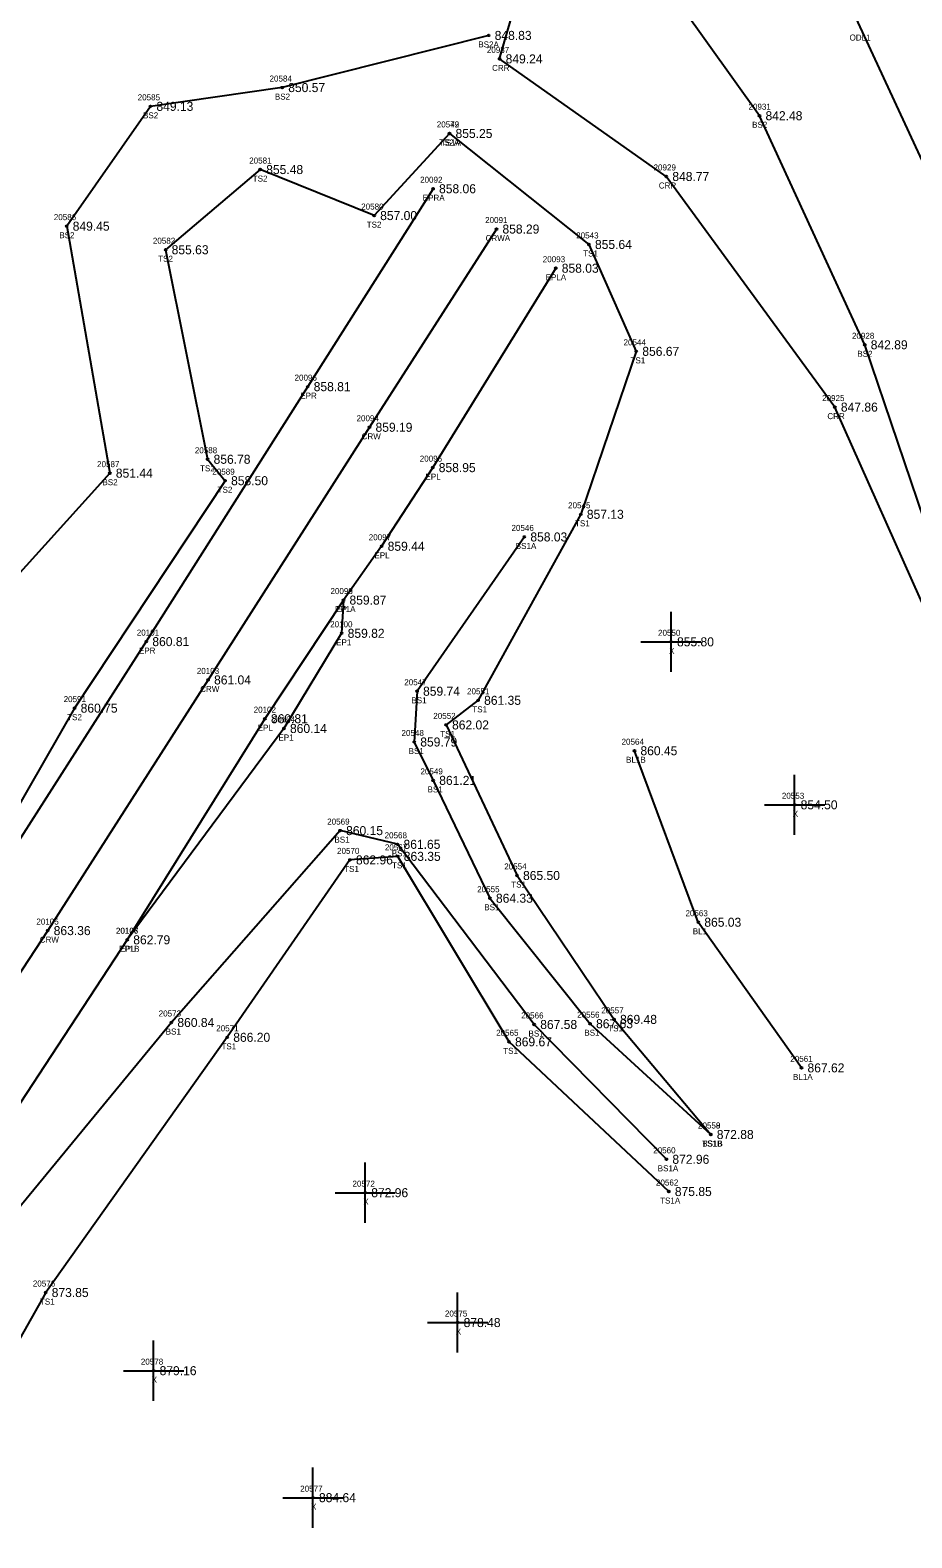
# Model space of a CAD drawing. Extents: x 1394668 to 1397182, y 1073212 to 1074501.
# Drawn here: x 1395802.6 to 1395949.1, y 1073687.4 to 1073938.1 of the extents above; entities that cross this region are included whole.
import ezdxf

# ---------------------------------------------------------------- set-up
doc = ezdxf.new("R2010")
doc.units = 0
for name, color, linetype in [('RD_DTM_BkLn1', 7, 'Continuous'), ('RD_DTM_BkLn2', 7, 'Continuous'), ('RD_DTM_BkLn_txCode', 7, 'Continuous'), ('RD_EX_H2O', 7, 'Continuous'), ('RD_EX_H2O_txCode', 7, 'Continuous'), ('RD_EX_Misc', 7, 'Continuous'), ('RD_EX_Misc_txCode', 7, 'Continuous'), ('RD_EX_Road', 7, 'Continuous'), ('RD_EX_Road_txCode', 7, 'Continuous'), ('RD_EX_TX_H2O_ELEV', 7, 'Continuous'), ('RD_EX_TX_Misc_ELEV', 7, 'Continuous'), ('RD_EX_TX_Road_ELEV', 7, 'Continuous'), ('RD_HC_Survey_ELEV', 7, 'Continuous'), ('RD_HC_Survey_txCode', 7, 'Continuous'), ('RD_SMD_Locator', 7, 'Continuous')]:
    doc.layers.add(name, color=color, linetype=linetype)

msp = doc.modelspace()

# ---------------------------------------------------------------- linework, layer by layer
at = {"layer": 'RD_DTM_BkLn1'}
for points in [[(1395880.09, 1073905.01), (1395858.99, 1073872.06), (1395832.15, 1073830.06), (1395805.49, 1073788.39), (1395778.2, 1073746.79), (1395749.91, 1073705.5), (1395721.01, 1073665.07), (1395690.33, 1073625.47), (1395658.02, 1073587.64), (1395622.95, 1073551.76), (1395585.52, 1073519.1), (1395545.34, 1073489.25), (1395503.34, 1073462.75), (1395459.17, 1073438.88), (1395413.72, 1073418.7), (1395366.56, 1073401.38), (1395319.05, 1073387), (1395269.86, 1073375.63), (1395220.56, 1073368.3)], [(1395930.8, 1073765.57), (1395913.65, 1073789.78), (1395903.03, 1073818.29)]]:
    msp.add_lwpolyline(points, dxfattribs=at)
at = {"layer": 'RD_DTM_BkLn2'}
for points in [[(1395957.8, 1073837.25), (1395941.31, 1073885.77), (1395923.82, 1073923.85), (1395893.58, 1073966.14), (1395870.08, 1073993.52)], [(1395878.8, 1073937.2), (1395844.48, 1073928.53), (1395822.57, 1073925.41), (1395808.65, 1073905.49), (1395815.82, 1073864.43), (1395791.04, 1073837.08), (1395769.09, 1073795.23), (1395741.94, 1073761.37), (1395712.42, 1073733.44), (1395686.92, 1073719.11), (1395655.83, 1073688.97), (1395630.94, 1073651.62), (1395607.03, 1073620.68), (1395575.39, 1073568.35), (1395560.35, 1073553.89), (1395550.78, 1073525.35), (1395509.42, 1073493.18)], [(1395872.29, 1073920.9), (1395859.76, 1073907.25), (1395840.82, 1073914.9), (1395825.1, 1073901.57), (1395832.07, 1073866.74), (1395834.98, 1073863.18), (1395809.97, 1073825.37), (1395786.91, 1073785.27), (1395760.58, 1073746.02), (1395733.77, 1073707.72), (1395713.02, 1073697.84), (1395686.96, 1073656.85), (1395662.51, 1073616.18), (1395631.74, 1073579.72), (1395598.58, 1073547.6), (1395556.36, 1073515.78), (1395517.25, 1073487.44)], [(1395872.29, 1073920.9), (1395895.47, 1073902.45), (1395903.34, 1073884.68), (1395894.12, 1073857.59), (1395877.04, 1073826.67), (1395871.71, 1073822.58), (1395883.51, 1073797.55), (1395899.64, 1073773.63), (1395915.72, 1073754.49)], [(1395884.73, 1073853.83), (1395866.89, 1073828.18), (1395866.43, 1073819.74), (1395869.58, 1073813.36), (1395879.01, 1073793.77), (1395895.65, 1073772.91), (1395915.72, 1073754.49)], [(1395908.34, 1073750.37), (1395886.37, 1073772.78), (1395863.64, 1073802.73), (1395854.1, 1073805.01), (1395826.05, 1073773.11), (1395793.87, 1073734.05), (1395764.78, 1073693.78), (1395736.01, 1073653.66), (1395704.56, 1073612.75), (1395670.33, 1073572.71), (1395637.43, 1073538.26), (1395595.47, 1073500.49), (1395545.21, 1073467.28)], [(1395908.75, 1073745.01), (1395882.18, 1073769.9), (1395863.69, 1073800.73), (1395855.74, 1073800.14), (1395835.34, 1073770.65), (1395805.16, 1073728.22), (1395777.09, 1073678.51), (1395754.62, 1073640.84), (1395721.66, 1073598.5), (1395682.88, 1073559.13), (1395644.57, 1073530.52), (1395608.93, 1073486.25), (1395561.12, 1073435.87)]]:
    msp.add_lwpolyline(points, dxfattribs=at)
at = {"layer": 'RD_EX_H2O'}
for points in [[(1395974.71, 1073847.23), (1395960.86, 1073894.92), (1395940.2, 1073939.35), (1395933.1, 1073958.35), (1395906.99, 1073983.95), (1395882.29, 1074009.48), (1395872.4, 1074025.84), (1395839.4, 1074068.55), (1395789.78, 1074092.35), (1395765.41, 1074131.47), (1395761.6, 1074177.86), (1395765.67, 1074225.67), (1395772.88, 1074279.07), (1395812.72, 1074333.02), (1395830.71, 1074357.92)], [(1395952, 1073840.27), (1395936.35, 1073875.41), (1395908.33, 1073913.75), (1395880.62, 1073933.3), (1395888.13, 1073959.38), (1395867.11, 1073990.5)]]:
    msp.add_lwpolyline(points, dxfattribs=at)
at = {"layer": 'RD_EX_Misc'}
for p, q in [((1395909.11, 1073831.39), (1395909.11, 1073841.39)), ((1395904.11, 1073836.39), (1395914.11, 1073836.39)), ((1395929.66, 1073804.3), (1395929.66, 1073814.3)), ((1395924.66, 1073809.3), (1395934.66, 1073809.3)), ((1395858.28, 1073739.82), (1395858.28, 1073749.82)), ((1395853.28, 1073744.82), (1395863.28, 1073744.82)), ((1395873.64, 1073718.23), (1395873.64, 1073728.23)), ((1395868.64, 1073723.23), (1395878.64, 1073723.23)), ((1395823.1, 1073710.23), (1395823.1, 1073720.23)), ((1395818.1, 1073715.23), (1395828.1, 1073715.23)), ((1395849.59, 1073689.12), (1395849.59, 1073699.12)), ((1395844.59, 1073694.12), (1395854.59, 1073694.12))]:
    msp.add_line(p, q, dxfattribs=at)
at = {"layer": 'RD_EX_Road'}
for points in [[(1395869.55, 1073911.71), (1395848.71, 1073878.81), (1395821.89, 1073836.43), (1395795.02, 1073794.57), (1395768.15, 1073753.29), (1395739.4, 1073711.73), (1395711.25, 1073671.91), (1395680.67, 1073632.3), (1395648.91, 1073595.47), (1395613.89, 1073559.5), (1395578.15, 1073528.43), (1395538.64, 1073499.26), (1395497.33, 1073473.22), (1395453.33, 1073449.12), (1395408.97, 1073429.57), (1395362.04, 1073412.34), (1395315.46, 1073398.44), (1395267.16, 1073387.31), (1395218.96, 1073380.11)], [(1395889.95, 1073898.5), (1395869.5, 1073865.35), (1395861.01, 1073852.28), (1395854.66, 1073843.33), (1395841.6, 1073823.61), (1395818.72, 1073786.86), (1395788.22, 1073740.4), (1395759.3, 1073697.79), (1395730.49, 1073656.98), (1395699.68, 1073617), (1395667.2, 1073579.48), (1395631.87, 1073543.45), (1395592.83, 1073509.92), (1395550.91, 1073478.97), (1395509.01, 1073452.5), (1395464.5, 1073428.26), (1395417.91, 1073407.56), (1395369.36, 1073389.54), (1395322.83, 1073375.66), (1395271.04, 1073363.5), (1395222.14, 1073356.32)], [(1395854.66, 1073843.33), (1395854.36, 1073837.81), (1395844.77, 1073821.99), (1395818.72, 1073786.86)]]:
    msp.add_lwpolyline(points, dxfattribs=at)
at = {"layer": 'RD_SMD_Locator'}
for centre in [(1395878.8, 1073937.2), (1395880.62, 1073933.3), (1395844.48, 1073928.53), (1395822.57, 1073925.41), (1395923.82, 1073923.85), (1395872.29, 1073920.9), (1395872.29, 1073920.9), (1395840.82, 1073914.9), (1395869.55, 1073911.71), (1395908.33, 1073913.75), (1395859.76, 1073907.25), (1395808.65, 1073905.49), (1395880.09, 1073905.01), (1395825.1, 1073901.57), (1395895.47, 1073902.45), (1395889.95, 1073898.5), (1395903.34, 1073884.68), (1395941.31, 1073885.77), (1395848.71, 1073878.81), (1395936.35, 1073875.41), (1395858.99, 1073872.06), (1395832.07, 1073866.74), (1395815.82, 1073864.43), (1395869.5, 1073865.35), (1395834.98, 1073863.18), (1395894.12, 1073857.59), (1395884.73, 1073853.83), (1395861.01, 1073852.28), (1395854.66, 1073843.33), (1395854.66, 1073843.33), (1395821.89, 1073836.43), (1395854.36, 1073837.81), (1395909.11, 1073836.39), (1395832.15, 1073830.06), (1395866.89, 1073828.18), (1395877.04, 1073826.67), (1395809.97, 1073825.37), (1395841.6, 1073823.61), (1395844.77, 1073821.99), (1395871.71, 1073822.58), (1395866.43, 1073819.74), (1395903.03, 1073818.29), (1395869.58, 1073813.36), (1395929.66, 1073809.3), (1395854.1, 1073805.01), (1395863.64, 1073802.73), (1395855.74, 1073800.14), (1395863.69, 1073800.73), (1395883.51, 1073797.55), (1395879.01, 1073793.77), (1395913.65, 1073789.78), (1395805.49, 1073788.39), (1395818.72, 1073786.86), (1395818.72, 1073786.86), (1395899.64, 1073773.63), (1395826.05, 1073773.11), (1395886.37, 1073772.78), (1395895.65, 1073772.91), (1395835.34, 1073770.65), (1395882.18, 1073769.9), (1395930.8, 1073765.57), (1395915.72, 1073754.49), (1395915.72, 1073754.49), (1395908.34, 1073750.37), (1395858.28, 1073744.82), (1395908.75, 1073745.01), (1395805.16, 1073728.22), (1395873.64, 1073723.23), (1395823.1, 1073715.23), (1395849.59, 1073694.12)]:
    msp.add_circle(centre, 0.15, dxfattribs=at)

# ---------------------------------------------------------------- texts
at = {"layer": 'RD_DTM_BkLn_txCode'}
for s, p in [('BS2A', (1395877.08, 1073935.2)), ('20584', (1395842.37, 1073929.53)), ('20585', (1395820.45, 1073926.41)), ('BS2', (1395843.26, 1073926.53)), ('BS2', (1395821.34, 1073923.41)), ('20931', (1395921.99, 1073924.85)), ('20542', (1395870.17, 1073921.9)), ('20579', (1395870.17, 1073921.9)), ('BS2', (1395922.59, 1073921.85)), ('TS2A', (1395870.56, 1073918.9)), ('TS1A', (1395870.84, 1073918.9)), ('20581', (1395838.99, 1073915.9)), ('TS2', (1395839.58, 1073912.9)), ('20580', (1395857.61, 1073908.25)), ('20586', (1395806.51, 1073906.49)), ('BS2', (1395807.42, 1073903.49)), ('TS2', (1395858.52, 1073905.25)), ('20543', (1395893.35, 1073903.45)), ('20582', (1395822.98, 1073902.57)), ('TS2', (1395823.86, 1073899.57)), ('TS1', (1395894.51, 1073900.45)), ('20544', (1395901.22, 1073885.68)), ('20928', (1395939.19, 1073886.77)), ('BS2', (1395940.08, 1073883.77)), ('TS1', (1395902.38, 1073882.68)), ('20588', (1395829.95, 1073867.74)), ('20587', (1395813.7, 1073865.43)), ('TS2', (1395830.82, 1073864.74)), ('20589', (1395832.86, 1073864.18)), ('BS2', (1395814.59, 1073862.43)), ('TS2', (1395833.74, 1073861.18)), ('20545', (1395892, 1073858.59)), ('TS1', (1395893.16, 1073855.59)), ('20546', (1395882.59, 1073854.83)), ('BS1A', (1395883.3, 1073851.83)), ('20547', (1395864.77, 1073829.18)), ('20591', (1395808.14, 1073826.37)), ('BS1', (1395865.95, 1073826.18)), ('20551', (1395875.2, 1073827.67)), ('TS2', (1395808.73, 1073823.37)), ('20552', (1395869.59, 1073823.58)), ('TS1', (1395876.08, 1073824.67)), ('20548', (1395864.31, 1073820.74)), ('TS1', (1395870.75, 1073820.58)), ('20564', (1395900.89, 1073819.29)), ('BS1', (1395865.49, 1073817.74)), ('BL1B', (1395901.64, 1073816.29)), ('20549', (1395867.46, 1073814.36)), ('BS1', (1395868.64, 1073811.36)), ('20569', (1395851.96, 1073806.01)), ('BS1', (1395853.16, 1073803.01)), ('20568', (1395861.5, 1073803.73)), ('20570', (1395853.59, 1073801.14)), ('20567', (1395861.55, 1073801.73)), ('BS1', (1395862.69, 1073800.73)), ('TS1', (1395854.78, 1073798.14)), ('TS1', (1395862.73, 1073798.73)), ('20554', (1395881.39, 1073798.55)), ('TS1', (1395882.55, 1073795.55)), ('20555', (1395876.89, 1073794.77)), ('BS1', (1395878.07, 1073791.77)), ('20563', (1395911.51, 1073790.78)), ('BL1', (1395912.73, 1073787.78)), ('20573', (1395823.94, 1073774.11)), ('20566', (1395884.2, 1073773.78)), ('20556', (1395893.51, 1073773.91)), ('20557', (1395897.52, 1073774.63)), ('BS1', (1395825.11, 1073771.11)), ('20571', (1395833.51, 1073771.65)), ('20565', (1395880.04, 1073770.9)), ('BS1', (1395885.42, 1073770.78)), ('BS1', (1395894.7, 1073770.91)), ('TS1', (1395898.68, 1073771.63)), ('TS1', (1395834.38, 1073768.65)), ('TS1', (1395881.22, 1073767.9)), ('20561', (1395928.94, 1073766.57)), ('BL1A', (1395929.39, 1073763.57)), ('20558', (1395913.6, 1073755.49)), ('20559', (1395913.6, 1073755.49)), ('20560', (1395906.15, 1073751.37)), ('TS1B', (1395914.28, 1073752.49)), ('BS1B', (1395914.3, 1073752.49)), ('BS1A', (1395906.9, 1073748.37)), ('20562', (1395906.61, 1073746.01)), ('TS1A', (1395907.3, 1073743.01)), ('20576', (1395803.02, 1073729.22)), ('TS1', (1395804.2, 1073726.22))]:
    msp.add_text(s, height=1, dxfattribs=at).set_placement(p)
at = {"layer": 'RD_EX_H2O_txCode'}
for s, p in [('ODL1', (1395938.79, 1073936.35)), ('20937', (1395878.5, 1073934.3)), ('CRR', (1395879.37, 1073931.3)), ('20929', (1395906.21, 1073914.75)), ('CRR', (1395907.08, 1073911.75)), ('20925', (1395934.23, 1073876.41)), ('CRR', (1395935.1, 1073873.41))]:
    msp.add_text(s, height=1, dxfattribs=at).set_placement(p)
at = {"layer": 'RD_EX_Misc_txCode'}
for s, p in [('20550', (1395906.95, 1073837.39)), ('X', (1395908.79, 1073834.39)), ('20553', (1395927.54, 1073810.3)), ('X', (1395929.34, 1073807.3)), ('20572', (1395856.16, 1073745.82)), ('X', (1395857.96, 1073742.82)), ('20575', (1395871.53, 1073724.23)), ('X', (1395873.33, 1073721.23)), ('20578', (1395820.98, 1073716.23)), ('X', (1395822.78, 1073713.23)), ('20577', (1395847.47, 1073695.12)), ('X', (1395849.27, 1073692.12))]:
    msp.add_text(s, height=1, dxfattribs=at).set_placement(p)
at = {"layer": 'RD_EX_Road_txCode'}
for s, p in [('20092', (1395867.4, 1073912.71)), ('EPRA', (1395867.84, 1073909.71)), ('20093', (1395887.79, 1073899.5)), ('EPLA', (1395888.26, 1073896.5)), ('20096', (1395846.53, 1073879.81)), ('EPR', (1395847.48, 1073876.81)), ('20095', (1395867.34, 1073866.35)), ('EPL', (1395868.29, 1073863.35)), ('20097', (1395858.86, 1073853.28)), ('EPL', (1395859.81, 1073850.28)), ('20098', (1395852.5, 1073844.33)), ('20099', (1395852.5, 1073844.33)), ('EP1A', (1395853.25, 1073841.33)), ('EPL', (1395853.45, 1073841.33)), ('20100', (1395852.45, 1073838.81)), ('20101', (1395820.3, 1073837.43)), ('EP1', (1395853.44, 1073835.81)), ('EPR', (1395820.66, 1073834.43)), ('20102', (1395839.73, 1073824.61)), ('20104', (1395842.9, 1073822.99)), ('EPL', (1395840.4, 1073821.61)), ('EP1', (1395843.85, 1073819.99)), ('20106', (1395816.82, 1073787.86)), ('20107', (1395816.85, 1073787.86)), ('EP1B', (1395817.33, 1073784.86)), ('EPL', (1395817.52, 1073784.86))]:
    msp.add_text(s, height=1, dxfattribs=at).set_placement(p)
at = {"layer": 'RD_EX_TX_H2O_ELEV'}
for s, p in [('849.24', (1395881.62, 1073932.55)), ('848.77', (1395909.33, 1073913)), ('847.86', (1395937.35, 1073874.66))]:
    msp.add_text(s, height=1.5, dxfattribs=at).set_placement(p)
at = {"layer": 'RD_EX_TX_Misc_ELEV'}
for s, p in [('848.83', (1395879.8, 1073936.45)), ('850.57', (1395845.48, 1073927.78)), ('849.13', (1395823.57, 1073924.66)), ('842.48', (1395924.82, 1073923.1)), ('855.25', (1395873.29, 1073920.15)), ('855.25', (1395873.29, 1073920.15)), ('855.48', (1395841.82, 1073914.15)), ('857.00', (1395860.76, 1073906.5)), ('849.45', (1395809.65, 1073904.74)), ('855.63', (1395826.1, 1073900.82)), ('855.64', (1395896.47, 1073901.7)), ('842.89', (1395942.31, 1073885.02)), ('856.67', (1395904.34, 1073883.93)), ('856.78', (1395833.07, 1073865.99)), ('851.44', (1395816.82, 1073863.68)), ('858.50', (1395835.98, 1073862.43)), ('857.13', (1395895.12, 1073856.84)), ('858.03', (1395885.73, 1073853.08)), ('855.80', (1395910.11, 1073835.64)), ('859.74', (1395867.89, 1073827.43)), ('861.35', (1395878.04, 1073825.92)), ('860.75', (1395810.97, 1073824.62)), ('862.02', (1395872.71, 1073821.83)), ('859.79', (1395867.43, 1073818.99)), ('860.45', (1395904.03, 1073817.54)), ('861.21', (1395870.58, 1073812.61)), ('854.50', (1395930.66, 1073808.55)), ('860.15', (1395855.1, 1073804.26)), ('861.65', (1395864.64, 1073801.98)), ('863.35', (1395864.69, 1073799.98)), ('862.96', (1395856.74, 1073799.39)), ('865.50', (1395884.51, 1073796.8)), ('864.33', (1395880.01, 1073793.02)), ('865.03', (1395914.65, 1073789.03)), ('860.84', (1395827.05, 1073772.36)), ('869.48', (1395900.64, 1073772.88)), ('866.20', (1395836.34, 1073769.9)), ('867.58', (1395887.37, 1073772.03)), ('867.63', (1395896.65, 1073772.16)), ('869.67', (1395883.18, 1073769.15)), ('867.62', (1395931.8, 1073764.82)), ('872.88', (1395916.72, 1073753.74)), ('872.88', (1395916.72, 1073753.74)), ('872.96', (1395909.34, 1073749.62)), ('872.96', (1395859.28, 1073744.07)), ('875.85', (1395909.75, 1073744.26)), ('873.85', (1395806.16, 1073727.47)), ('878.48', (1395874.64, 1073722.48)), ('879.16', (1395824.1, 1073714.48)), ('884.64', (1395850.59, 1073693.37))]:
    msp.add_text(s, height=1.5, dxfattribs=at).set_placement(p)
at = {"layer": 'RD_EX_TX_Road_ELEV'}
for s, p in [('858.06', (1395870.55, 1073910.96)), ('858.03', (1395890.95, 1073897.75)), ('858.81', (1395849.71, 1073878.06)), ('858.95', (1395870.5, 1073864.6)), ('859.44', (1395862.01, 1073851.53)), ('859.87', (1395855.66, 1073842.58)), ('859.87', (1395855.66, 1073842.58)), ('860.81', (1395822.89, 1073835.68)), ('859.82', (1395855.36, 1073837.06)), ('860.81', (1395842.6, 1073822.86)), ('860.14', (1395845.77, 1073821.24)), ('862.79', (1395819.72, 1073786.11)), ('862.79', (1395819.72, 1073786.11))]:
    msp.add_text(s, height=1.5, dxfattribs=at).set_placement(p)
at = {"layer": 'RD_HC_Survey_ELEV'}
for s, p in [('858.29', (1395881.09, 1073904.26)), ('859.19', (1395859.99, 1073871.31)), ('861.04', (1395833.15, 1073829.31)), ('863.36', (1395806.49, 1073787.64))]:
    msp.add_text(s, height=1.5, dxfattribs=at).set_placement(p)
at = {"layer": 'RD_HC_Survey_txCode'}
for s, p in [('20091', (1395878.21, 1073906.01)), ('CRWA', (1395878.29, 1073903.01)), ('20094', (1395856.83, 1073873.06)), ('CRW', (1395857.68, 1073870.06)), ('20103', (1395830.28, 1073831.06)), ('CRW', (1395830.84, 1073828.06)), ('20105', (1395803.61, 1073789.39)), ('CRW', (1395804.17, 1073786.39))]:
    msp.add_text(s, height=1, dxfattribs=at).set_placement(p)

doc.saveas('drawing.dxf')
